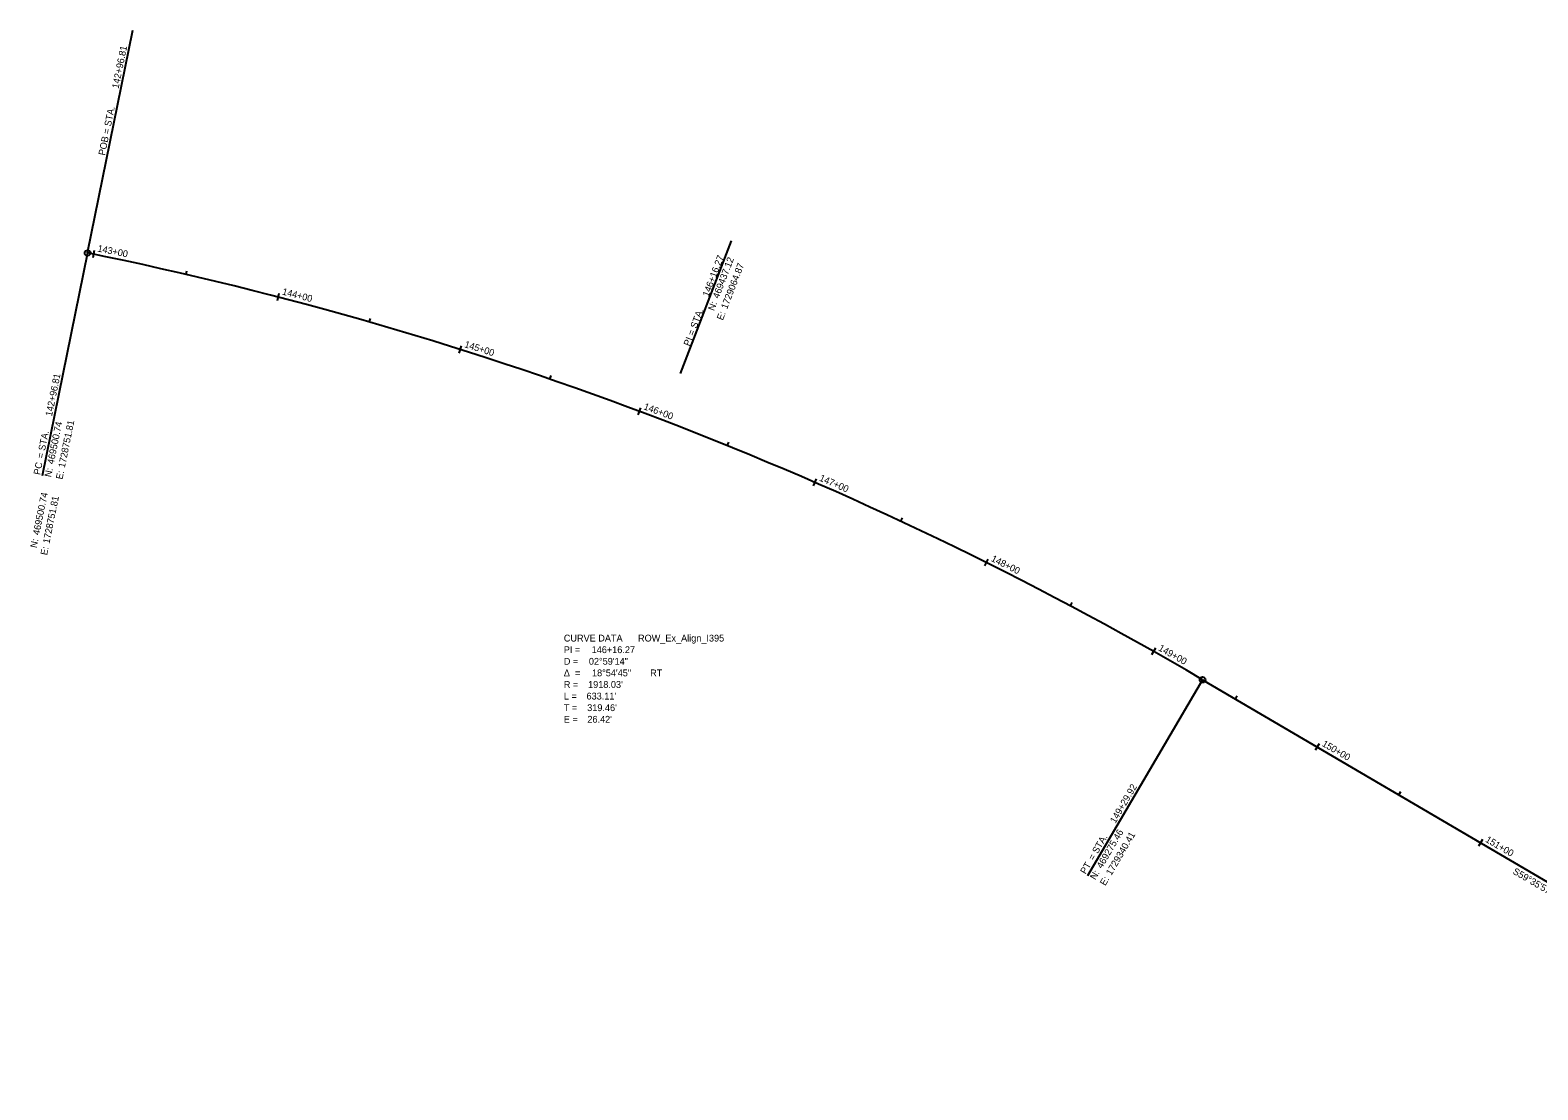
# Model space of a CAD drawing. Extents: x 1728722 to 1745262, y 461772 to 469775.
# Drawn here: x 1728722 to 1729517, y 469059 to 469618 of the extents above; entities that cross this region are included whole.
import ezdxf

# ---------------------------------------------------------------- set-up
doc = ezdxf.new("R2010")
doc.units = 0
for name, color, linetype in [('E_ROW_Baseline', 7, 'Continuous'), ('E_ROW_Baseline_Bearings', 7, 'Continuous'), ('E_ROW_Baseline_CurveData', 7, 'Continuous'), ('E_ROW_Baseline_Flags', 7, 'Continuous'), ('E_ROW_Baseline_Text', 7, 'Continuous'), ('E_ROW_Baseline_XY_Text', 7, 'Continuous')]:
    doc.layers.add(name, color=color, linetype=linetype)

msp = doc.modelspace()

# ---------------------------------------------------------------- linework, layer by layer
at = {"layer": 'E_ROW_Baseline'}
msp.add_line((1729340.41, 469275.46), (1729709.29, 469059.03), dxfattribs=at)
msp.add_line((1729340.41, 469275.46), (1729709.29, 469059.03), dxfattribs=at)
msp.add_arc((1728369.8, 467621.14), 1918.03, 59.59936, 78.51177, dxfattribs=at)
msp.add_arc((1728369.8, 467621.14), 1918.03, 59.59936, 78.51177, dxfattribs=at)
at = {"layer": 'E_ROW_Baseline_Flags'}
for p, q in [((1728751.81, 469500.74), (1728775.71, 469618.34)), ((1728775.71, 469618.34), (1728775.71, 469618.34)), ((1729064.87, 469437.12), (1729091.68, 469507.16)), ((1729091.68, 469507.16), (1729091.68, 469507.16)), ((1728751.81, 469500.74), (1728727.91, 469383.15)), ((1728751.81, 469500.74), (1728751.81, 469500.74)), ((1728727.91, 469383.15), (1728727.91, 469383.15)), ((1729340.41, 469275.46), (1729279.68, 469171.96)), ((1729340.41, 469275.46), (1729340.41, 469275.46)), ((1729279.68, 469171.96), (1729279.68, 469171.96))]:
    msp.add_line(p, q, dxfattribs=at)
for centre in [(1728751.81, 469500.74), (1729340.41, 469275.46)]:
    msp.add_circle(centre, 1.5, dxfattribs=at)
at = {"layer": 'E_ROW_Baseline_Text'}
for p, q in [((1728755.34, 469502.08), (1728754.53, 469498.16)), ((1728803.78, 469489.43), (1728804.23, 469491.39)), ((1728852.83, 469479.43), (1728851.83, 469475.56)), ((1728900.55, 469464.27), (1728901.11, 469466.21)), ((1728949.02, 469451.73), (1728947.81, 469447.92)), ((1728995.88, 469434.11), (1728996.54, 469436.01)), ((1729043.63, 469419.06), (1729042.23, 469415.31)), ((1729089.51, 469399.02), (1729090.26, 469400.88)), ((1729136.41, 469381.5), (1729134.81, 469377.83)), ((1729181.18, 469359.1), (1729182.03, 469360.92)), ((1729227.11, 469339.16), (1729225.32, 469335.58)), ((1729270.65, 469314.45), (1729271.6, 469316.23)), ((1729315.47, 469292.15), (1729313.5, 469288.67)), ((1729357.72, 469265.3), (1729358.74, 469267.03)), ((1729401.87, 469241.73), (1729399.84, 469238.28)), ((1729443.98, 469214.69), (1729444.99, 469216.43)), ((1729488.12, 469191.12), (1729486.09, 469187.67))]:
    msp.add_line(p, q, dxfattribs=at)

# ---------------------------------------------------------------- texts
at = {"layer": 'E_ROW_Baseline_Bearings'}
msp.add_text('S59°35\'57.7"E', height=3.6, rotation=329.59936, dxfattribs=at).set_placement((1729503.82, 469173.32))
at = {"layer": 'E_ROW_Baseline_CurveData'}
for s, p in [('CURVE DATA ', (1729003.21, 469295.65)), ('ROW_Ex_Align_I395', (1729042.38, 469295.65)), ('PI = ', (1729003.21, 469289.53)), ('146+16.27', (1729017.91, 469289.53)), ('D = ', (1729003.21, 469283.41)), ('02°59\'14"', (1729016.45, 469283.41)), ('Δ  = ', (1729003.21, 469277.29)), ('R = ', (1729003.21, 469271.17)), ("1918.03'", (1729016.02, 469271.17)), ('18°54\'45"', (1729018.09, 469277.29)), (' RT', (1729047.46, 469277.29)), ('L = ', (1729003.21, 469265.05)), ("633.11'", (1729015.21, 469265.05)), ('T = ', (1729003.21, 469258.93)), ("319.46'", (1729015.56, 469258.93)), ('E = ', (1729003.21, 469252.81)), ("26.42'", (1729015.65, 469252.81))]:
    msp.add_text(s, height=3.6, dxfattribs=at).set_placement(p)
at = {"layer": 'E_ROW_Baseline_Flags'}
for s, rotation, p in [('142+96.81', 78.51177, (1728768.17, 469587.3)), ('POB = STA. ', 78.51177, (1728761, 469551.99)), ('142+96.81', 78.51177, (1728733.02, 469414.31)), (' = STA. ', 78.51177, (1728728.23, 469390.76)), ('PC', 78.51177, (1728726.73, 469383.39)), ('149+29.92', 59.59936, (1729294.37, 469199.37)), (' = STA. ', 59.59936, (1729282.21, 469178.64)), ('PT', 59.59936, (1729278.65, 469172.56))]:
    msp.add_text(s, height=3.6, rotation=rotation, dxfattribs=at).set_placement(p)
at = {"layer": 'E_ROW_Baseline_Text'}
for s, rotation, p in [('143+00', 348.41648, (1728756.82, 469501.56)), ('146+16.27', 69.05556, (1729079.62, 469477.33)), ('144+00', 345.42925, (1728854.29, 469478.83)), ('PI = STA.', 69.05556, (1729069.64, 469451.26)), ('145+00', 342.44203, (1728950.44, 469451.06)), ('146+00', 339.45481, (1729045.02, 469418.31)), ('147+00', 336.46758, (1729137.76, 469380.68)), ('148+00', 333.48036, (1729228.41, 469338.27)), ('149+00', 330.49314, (1729316.73, 469291.19)), ('150+00', 329.59936, (1729403.11, 469240.76)), ('151+00', 329.59936, (1729489.36, 469190.15))]:
    msp.add_text(s, height=3.6, rotation=rotation, dxfattribs=at).set_placement(p)
at = {"layer": 'E_ROW_Baseline_XY_Text'}
for s, rotation, p in [('469437.12', 69.05556, (1729084.99, 469476.42)), ('1729064.87', 69.05556, (1729089.39, 469470.79)), ('N:', 69.05556, (1729082.5, 469469.94)), ('E:', 69.05556, (1729087.14, 469464.93)), ('469500.74', 78.51177, (1728733.93, 469389.01)), ('1728751.81', 78.51177, (1728739.8, 469387.13)), ('N:', 78.51177, (1728732.55, 469382.2)), ('E:', 78.51177, (1728738.55, 469380.99)), ('469500.74', 78.51177, (1728726.34, 469351.63)), ('1728751.81', 78.51177, (1728731.67, 469347.14)), ('N:', 78.51177, (1728724.96, 469344.83)), ('E:', 78.51177, (1728730.42, 469340.99)), ('469275.46', 59.59936, (1729287.28, 469175.55)), ('1729340.41', 59.59936, (1729292.22, 469171.87)), ('N:', 59.59936, (1729283.77, 469169.56)), ('E:', 59.59936, (1729289.05, 469166.46))]:
    msp.add_text(s, height=3.6, rotation=rotation, dxfattribs=at).set_placement(p)

doc.saveas('drawing.dxf')
